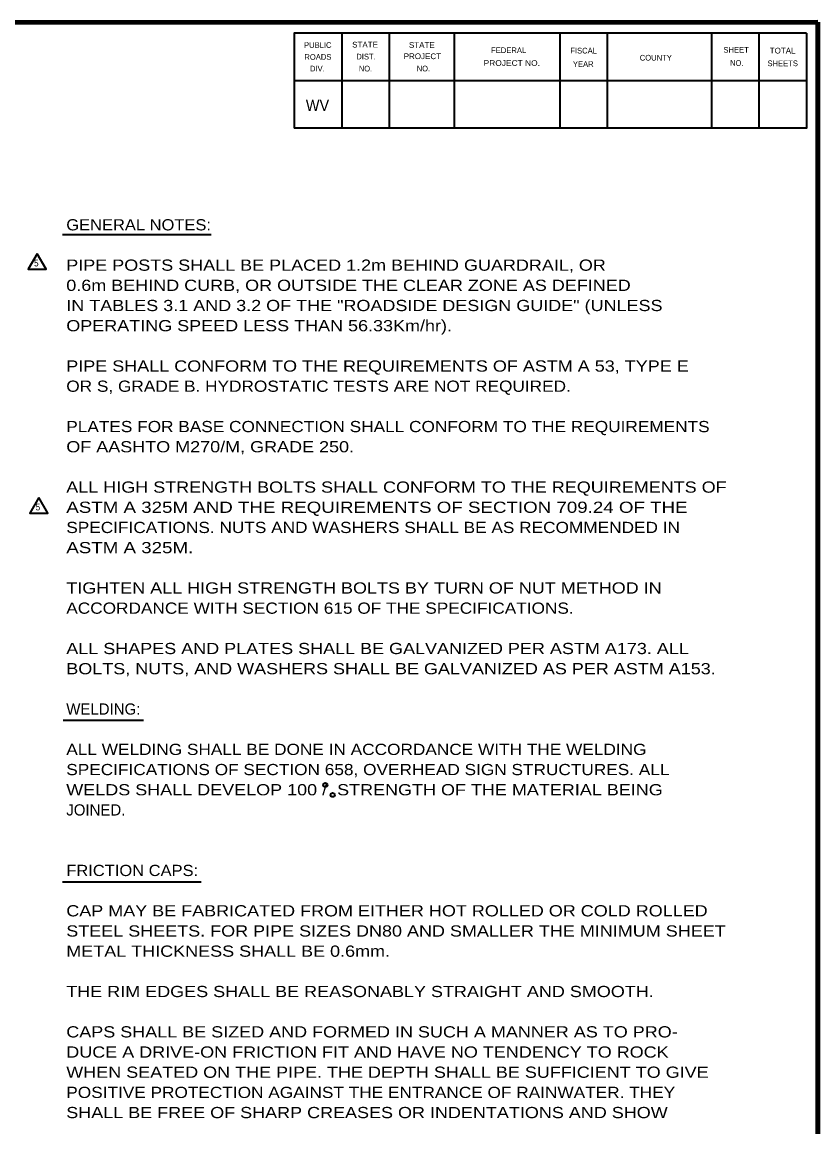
# Model space of a CAD drawing. Extents: x -274 to 582, y -298 to 246.
# Drawn here: x 362.2 to 575.3, y -55.7 to 240 of the extents above; entities that cross this region are included whole.
import ezdxf
from ezdxf.enums import TextEntityAlignment as Align

# ---------------------------------------------------------------- set-up
doc = ezdxf.new("R2010")
doc.units = 0
doc.header["$LTSCALE"] = 1.2
doc.layers.add('1', color=7, linetype='Continuous', lineweight=53)
doc.layers.add('61', color=7, linetype='Continuous', lineweight=35)

msp = doc.modelspace()

# ---------------------------------------------------------------- linework, layer by layer
at = {"layer": '1', "lineweight": 158}
msp.add_line((575.293, -286.139), (575.293, 239.961), dxfattribs=at)
at = {"layer": '1', "lineweight": 13}
msp.add_line((575.293, -286.139), (575.293, 239.961), dxfattribs=at)
at = {"layer": '1', "lineweight": 35}
for p, q in [((373.029, 183.149), (412.86, 183.149)), ((373.241, 53.165), (394.74, 53.165)), ((373.049, 9.831), (410.148, 9.831))]:
    msp.add_line(p, q, dxfattribs=at)
at = {"layer": '1', "lineweight": 158}
msp.add_lwpolyline([(575.293, 239.961), (-216.407, 239.861), (-216.307, -286.139)], dxfattribs=at)
at = {"layer": '1', "lineweight": 35}
for points in [[(366.263, 177.98), (363.863, 173.823), (368.663, 173.823)], [(366.686, 112.695), (364.286, 108.538), (369.086, 108.538)]]:
    msp.add_lwpolyline(points, close=True, dxfattribs=at)
for centre in [(443.403, 35.787), (445.364, 33.125)]:
    msp.add_circle(centre, 0.546, dxfattribs=at)
at = {"layer": '61'}
for p, q in [((447.793, 236.961), (447.793, 211.561)), ((460.493, 236.961), (460.493, 211.561)), ((477.893, 236.961), (477.893, 211.561)), ((506.193, 236.961), (506.193, 211.561)), ((518.893, 236.961), (518.893, 211.561)), ((546.793, 236.961), (546.793, 211.561)), ((559.493, 236.961), (559.493, 211.561)), ((572.193, 224.261), (435.093, 224.261))]:
    msp.add_line(p, q, dxfattribs=at)
for points in [[(572.193, 236.961), (435.093, 236.961), (435.093, 211.561)], [(572.193, 236.961), (572.193, 211.561), (435.093, 211.561)]]:
    msp.add_lwpolyline(points, dxfattribs=at)

# ---------------------------------------------------------------- texts
at = {"layer": '1'}
for s, height, width, p in [('WV', 3.048, 0.95, (438.193, 216.161)), ('GENERAL NOTES:', 3, 1.1, (374.048, 184.213)), ('PIPE POSTS SHALL BE PLACED 1.2m BEHIND GUARDRAIL, OR', 3, 1.2, (374.048, 173.413)), ('0.6m BEHIND CURB, OR OUTSIDE THE CLEAR ZONE AS DEFINED', 3, 1.2, (374.048, 168.013)), ('IN TABLES 3.1 AND 3.2 OF THE "ROADSIDE DESIGN GUIDE" (UNLESS', 3, 1.2, (374.048, 162.613)), ('OPERATING SPEED LESS THAN 56.33Km/hr).', 3, 1.2, (374.048, 157.213)), ('PIPE SHALL CONFORM TO THE REQUIREMENTS OF ASTM A 53, TYPE E', 3, 1.2, (374.048, 146.413)), ('OR S, GRADE B. HYDROSTATIC TESTS ARE NOT REQUIRED.', 3, 1.15, (374.048, 141.013)), ('PLATES FOR BASE CONNECTION SHALL CONFORM TO THE REQUIREMENTS', 3, 1.15, (374.048, 130.213)), ('OF AASHTO M270/M, GRADE 250.', 3, 1.2, (374.048, 124.813)), ('ALL HIGH STRENGTH BOLTS SHALL CONFORM TO THE REQUIREMENTS OF', 3, 1.2, (374.048, 114.013)), ('ASTM A 325M AND THE REQUIREMENTS OF SECTION 709.24 OF THE', 3, 1.25, (374.048, 108.613)), ('SPECIFICATIONS. NUTS AND WASHERS SHALL BE AS RECOMMENDED IN', 3, 1.15, (374.048, 103.213)), ('ASTM A 325M.', 3, 1.25, (374.048, 97.813)), ('TIGHTEN ALL HIGH STRENGTH BOLTS BY TURN OF NUT METHOD IN', 3, 1.2, (374.048, 87.013)), ('ACCORDANCE WITH SECTION 615 OF THE SPECIFICATIONS.', 3, 1.15, (374.048, 81.613)), ('ALL SHAPES AND PLATES SHALL BE GALVANIZED PER ASTM A173. ALL', 3, 1.2, (374.048, 70.813)), ('BOLTS, NUTS, AND WASHERS SHALL BE GALVANIZED AS PER ASTM A153.', 3, 1.2, (374.048, 65.413)), ('ALL WELDING SHALL BE DONE IN ACCORDANCE WITH THE WELDING', 3, 1.15, (374.048, 43.813)), ('SPECIFICATIONS OF SECTION 658, OVERHEAD SIGN STRUCTURES. ALL', 3, 1.15, (374.048, 38.413)), ('WELDS SHALL DEVELOP 100 /  STRENGTH OF THE MATERIAL BEING', 3, 1.2, (374.048, 33.013)), ('FRICTION CAPS:', 3, 1.1, (374.048, 11.413)), ('CAP MAY BE FABRICATED FROM EITHER HOT ROLLED OR COLD ROLLED', 3, 1.2, (374.048, 0.613)), ('STEEL SHEETS. FOR PIPE SIZES DN80 AND SMALLER THE MINIMUM SHEET', 3, 1.2, (374.048, -4.787)), ('METAL THICKNESS SHALL BE 0.6mm.', 3, 1.2, (374.048, -10.187)), ('THE RIM EDGES SHALL BE REASONABLY STRAIGHT AND SMOOTH.', 3, 1.2, (374.048, -20.987)), ('CAPS SHALL BE SIZED AND FORMED IN SUCH A MANNER AS TO PRO-', 3, 1.2, (374.048, -31.787)), ('DUCE A DRIVE-ON FRICTION FIT AND HAVE NO TENDENCY TO ROCK', 3, 1.2, (374.048, -37.187)), ('WHEN SEATED ON THE PIPE. THE DEPTH SHALL BE SUFFICIENT TO GIVE', 3, 1.2, (374.048, -42.587)), ('POSITIVE PROTECTION AGAINST THE ENTRANCE OF RAINWATER. THEY', 3, 1.15, (374.048, -47.987)), ('SHALL BE FREE OF SHARP CREASES OR INDENTATIONS AND SHOW', 3, 1.2, (374.048, -53.387))]:
    msp.add_text(s, height=height, dxfattribs=dict(at, width=width)).set_placement(p)
at = {"layer": '1', "width": 0.9}
for p in [(366.032, 174.567), (366.454, 109.282)]:
    msp.add_text('5', height=1.8, dxfattribs=at).set_placement(p, align=Align.CENTER)
at = {"layer": '1'}
for s, p in [('WELDING:', (374.048, 54.613)), ('JOINED.', (374.048, 27.613))]:
    msp.add_text(s, height=3, dxfattribs=at).set_placement(p)
at = {"layer": '61'}
for s, height, rotation, p in [('PUBLIC', 1.525, 0.033, (437.693, 233.061)), ('ROADS', 1.525, 0.124, (437.793, 229.861)), ('DIST.', 1.525, 0.056, (451.693, 229.961)), ('FEDERAL', 1.523, 0.007, (487.793, 231.661)), ('FISCAL', 1.525, 359.942, (508.993, 231.561)), ('COUNTY', 1.523, 0.069, (527.593, 229.661)), ('SHEET', 1.525, 0.059, (549.993, 231.761)), ('DIV.', 1.525, 359.932, (439.293, 226.761)), ('YEAR', 1.523, 0.105, (509.693, 227.961)), ('SHEETS', 1.523, 359.959, (561.793, 228.161))]:
    msp.add_text(s, height=height, rotation=rotation, dxfattribs=at).set_placement(p)
for s, rotation, width, p in [('STATE', 0.059, 1.05, (450.593, 233.161)), ('STATE', 0.059, 1.05, (465.793, 233.061)), ('PROJECT', 359.908, 1.05, (464.393, 230.061)), ('TOTAL', 359.926, 1.05, (562.393, 231.561)), ('NO.', 359.852, 0.9, (452.393, 226.761)), ('NO.', 0.225, 0.9, (467.893, 226.761)), ('PROJECT NO.', 359.922, 1.1, (485.793, 228.261)), ('NO.', 359.852, 0.9, (551.793, 228.261))]:
    msp.add_text(s, height=1.525, rotation=rotation, dxfattribs=dict(at, width=width)).set_placement(p)

doc.saveas('drawing.dxf')
